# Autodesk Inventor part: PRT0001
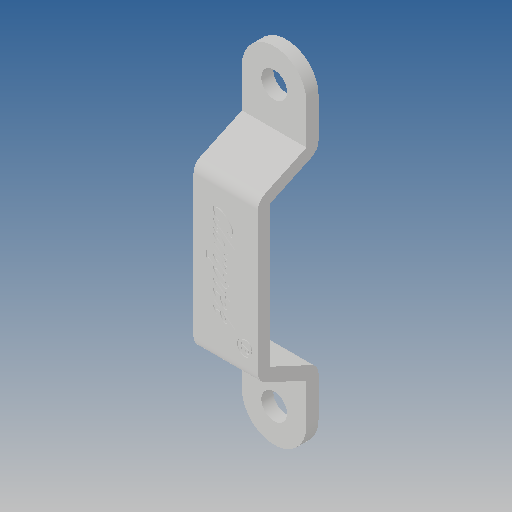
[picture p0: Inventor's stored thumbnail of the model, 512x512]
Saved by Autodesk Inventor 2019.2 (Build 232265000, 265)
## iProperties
Created: 2012-06
Part Number: PRT0001
Material: Ogólny
Document SubType Name: Modeling
Designer: CADENGINEERING4
Density: 1 g/cm^3
Appearance: Domyślna
Author: CADENGINEERING4
Revision Number: 1LAST_VERSION
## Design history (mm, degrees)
feature "Baza1"
node "Bryła1"
